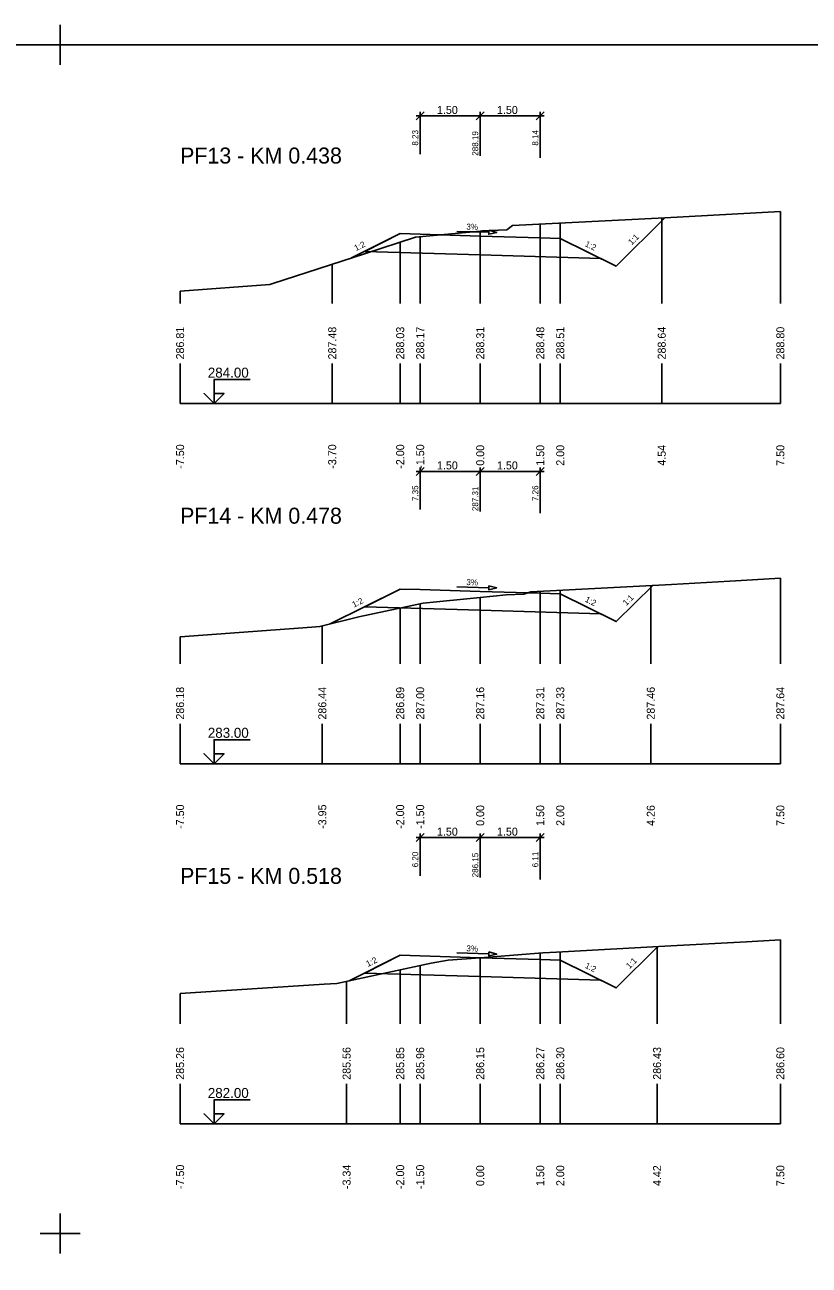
# Model space of a CAD drawing. Extents: x -5 to 1265, y -2 to 602.
# Drawn here: x 831.2 to 1027.2, y 291.7 to 601.7 of the extents above; entities that cross this region are included whole.
import ezdxf

# ---------------------------------------------------------------- set-up
doc = ezdxf.new("R2010")
doc.units = 0
for name, color, linetype in [('KOTA', 7, 'Continuous'), ('KOTA_DELKY', 7, 'Continuous'), ('KOTA_DELKY_CONT', 7, 'Continuous'), ('NS_TELESO_VOZOVKY', 7, 'Continuous'), ('NS_V_PF', 7, 'Continuous'), ('REZY_PF_PUVODNI', 7, 'Continuous'), ('SESTAVY_REZU_PF', 7, 'Continuous'), ('SKLON', 7, 'Continuous'), ('SVK', 7, 'Continuous')]:
    doc.layers.add(name, color=color, linetype=linetype)

msp = doc.modelspace()

# ---------------------------------------------------------------- linework, layer by layer
for p, q in [((840, 601.67), (840, 591.67)), ((840, 601.67), (840, 591.67)), ((840, 601.67), (840, 591.67)), ((840, 601.67), (840, 591.67)), ((840, 601.67), (840, 591.67)), ((840, 601.67), (840, 591.67)), ((840, 601.67), (840, 591.67)), ((840, 601.67), (840, 591.67)), ((840, 601.67), (840, 591.67)), ((840, 601.67), (840, 591.67)), ((840, 601.67), (840, 591.67)), ((840, 601.67), (840, 591.67)), ((840, 601.67), (840, 591.67)), ((840, 601.67), (840, 591.67)), ((840, 601.67), (840, 591.67)), ((840, 601.67), (840, 591.67)), ((840, 601.67), (840, 591.67)), ((840, 601.67), (840, 591.67)), ((840, 601.67), (840, 591.67)), ((840, 601.67), (840, 591.67)), ((840, 601.67), (840, 591.67)), ((840, 601.67), (840, 591.67)), ((840, 601.67), (840, 591.67)), ((840, 601.67), (840, 591.67)), ((840, 601.67), (840, 591.67)), ((840, 601.67), (840, 591.67)), ((840, 601.67), (840, 591.67)), ((840, 601.67), (840, 591.67)), ((840, 601.67), (840, 591.67)), ((840, 601.67), (840, 591.67)), ((840, 601.67), (840, 591.67)), ((840, 601.67), (840, 591.67)), ((840, 601.67), (840, 591.67)), ((840, 601.67), (840, 591.67)), ((840, 601.67), (840, 591.67)), ((840, 601.67), (840, 591.67)), ((840, 601.67), (840, 591.67)), ((840, 601.67), (840, 591.67)), ((840, 601.67), (840, 591.67)), ((840, 601.67), (840, 591.67)), ((840, 601.67), (840, 591.67)), ((840, 601.67), (840, 591.67)), ((840, 601.67), (840, 591.67)), ((840, 601.67), (840, 591.67)), ((840, 601.67), (840, 591.67)), ((840, 601.67), (840, 591.67)), ((840, 601.67), (840, 591.67)), ((840, 601.67), (840, 591.67)), ((840, 601.67), (840, 591.67)), ((840, 601.67), (840, 591.67)), ((840, 601.67), (840, 591.67)), ((840, 601.67), (840, 591.67)), ((840, 601.67), (840, 591.67)), ((840, 601.67), (840, 591.67)), ((845, 596.67), (835, 596.67)), ((845, 596.67), (835, 596.67)), ((845, 596.67), (835, 596.67)), ((845, 596.67), (835, 596.67)), ((845, 596.67), (835, 596.67)), ((845, 596.67), (835, 596.67)), ((845, 596.67), (835, 596.67)), ((845, 596.67), (835, 596.67)), ((845, 596.67), (835, 596.67)), ((845, 596.67), (835, 596.67)), ((845, 596.67), (835, 596.67)), ((845, 596.67), (835, 596.67)), ((845, 596.67), (835, 596.67)), ((845, 596.67), (835, 596.67)), ((845, 596.67), (835, 596.67)), ((845, 596.67), (835, 596.67)), ((845, 596.67), (835, 596.67)), ((845, 596.67), (835, 596.67)), ((845, 596.67), (835, 596.67)), ((845, 596.67), (835, 596.67)), ((845, 596.67), (835, 596.67)), ((845, 596.67), (835, 596.67)), ((845, 596.67), (835, 596.67)), ((845, 596.67), (835, 596.67)), ((845, 596.67), (835, 596.67)), ((845, 596.67), (835, 596.67)), ((845, 596.67), (835, 596.67)), ((845, 596.67), (835, 596.67)), ((845, 596.67), (835, 596.67)), ((845, 596.67), (835, 596.67)), ((845, 596.67), (835, 596.67)), ((845, 596.67), (835, 596.67)), ((845, 596.67), (835, 596.67)), ((845, 596.67), (835, 596.67)), ((845, 596.67), (835, 596.67)), ((845, 596.67), (835, 596.67)), ((845, 596.67), (835, 596.67)), ((845, 596.67), (835, 596.67)), ((845, 596.67), (835, 596.67)), ((845, 596.67), (835, 596.67)), ((845, 596.67), (835, 596.67)), ((845, 596.67), (835, 596.67)), ((845, 596.67), (835, 596.67)), ((845, 596.67), (835, 596.67)), ((845, 596.67), (835, 596.67)), ((845, 596.67), (835, 596.67)), ((845, 596.67), (835, 596.67)), ((845, 596.67), (835, 596.67)), ((845, 596.67), (835, 596.67)), ((845, 596.67), (835, 596.67)), ((845, 596.67), (835, 596.67)), ((845, 596.67), (835, 596.67)), ((845, 596.67), (835, 596.67)), ((845, 596.67), (835, 596.67)), ((840, 304.67), (840, 294.67)), ((840, 304.67), (840, 294.67)), ((840, 304.67), (840, 294.67)), ((840, 304.67), (840, 294.67)), ((840, 304.67), (840, 294.67)), ((840, 304.67), (840, 294.67)), ((840, 304.67), (840, 294.67)), ((840, 304.67), (840, 294.67)), ((840, 304.67), (840, 294.67)), ((840, 304.67), (840, 294.67)), ((840, 304.67), (840, 294.67)), ((840, 304.67), (840, 294.67)), ((840, 304.67), (840, 294.67)), ((840, 304.67), (840, 294.67)), ((840, 304.67), (840, 294.67)), ((840, 304.67), (840, 294.67)), ((840, 304.67), (840, 294.67)), ((840, 304.67), (840, 294.67)), ((840, 304.67), (840, 294.67)), ((840, 304.67), (840, 294.67)), ((840, 304.67), (840, 294.67)), ((840, 304.67), (840, 294.67)), ((840, 304.67), (840, 294.67)), ((840, 304.67), (840, 294.67)), ((840, 304.67), (840, 294.67)), ((840, 304.67), (840, 294.67)), ((840, 304.67), (840, 294.67)), ((840, 304.67), (840, 294.67)), ((840, 304.67), (840, 294.67)), ((840, 304.67), (840, 294.67)), ((840, 304.67), (840, 294.67)), ((840, 304.67), (840, 294.67)), ((840, 304.67), (840, 294.67)), ((840, 304.67), (840, 294.67)), ((840, 304.67), (840, 294.67)), ((840, 304.67), (840, 294.67)), ((840, 304.67), (840, 294.67)), ((840, 304.67), (840, 294.67)), ((840, 304.67), (840, 294.67)), ((840, 304.67), (840, 294.67)), ((840, 304.67), (840, 294.67)), ((840, 304.67), (840, 294.67)), ((840, 304.67), (840, 294.67)), ((840, 304.67), (840, 294.67)), ((840, 304.67), (840, 294.67)), ((840, 304.67), (840, 294.67)), ((840, 304.67), (840, 294.67)), ((840, 304.67), (840, 294.67)), ((840, 304.67), (840, 294.67)), ((840, 304.67), (840, 294.67)), ((840, 304.67), (840, 294.67)), ((840, 304.67), (840, 294.67)), ((840, 304.67), (840, 294.67)), ((840, 304.67), (840, 294.67)), ((840, 304.67), (840, 294.67)), ((840, 304.67), (840, 294.67)), ((840, 304.67), (840, 294.67)), ((840, 304.67), (840, 294.67)), ((840, 304.67), (840, 294.67)), ((840, 304.67), (840, 294.67)), ((840, 304.67), (840, 294.67)), ((840, 304.67), (840, 294.67)), ((840, 304.67), (840, 294.67)), ((840, 304.67), (840, 294.67)), ((840, 304.67), (840, 294.67)), ((840, 304.67), (840, 294.67)), ((845, 299.67), (835, 299.67)), ((845, 299.67), (835, 299.67)), ((845, 299.67), (835, 299.67)), ((845, 299.67), (835, 299.67)), ((845, 299.67), (835, 299.67)), ((845, 299.67), (835, 299.67)), ((845, 299.67), (835, 299.67)), ((845, 299.67), (835, 299.67)), ((845, 299.67), (835, 299.67)), ((845, 299.67), (835, 299.67)), ((845, 299.67), (835, 299.67)), ((845, 299.67), (835, 299.67)), ((845, 299.67), (835, 299.67)), ((845, 299.67), (835, 299.67)), ((845, 299.67), (835, 299.67)), ((845, 299.67), (835, 299.67)), ((845, 299.67), (835, 299.67)), ((845, 299.67), (835, 299.67)), ((845, 299.67), (835, 299.67)), ((845, 299.67), (835, 299.67)), ((845, 299.67), (835, 299.67)), ((845, 299.67), (835, 299.67)), ((845, 299.67), (835, 299.67)), ((845, 299.67), (835, 299.67)), ((845, 299.67), (835, 299.67)), ((845, 299.67), (835, 299.67)), ((845, 299.67), (835, 299.67)), ((845, 299.67), (835, 299.67)), ((845, 299.67), (835, 299.67)), ((845, 299.67), (835, 299.67)), ((845, 299.67), (835, 299.67)), ((845, 299.67), (835, 299.67)), ((845, 299.67), (835, 299.67)), ((845, 299.67), (835, 299.67)), ((845, 299.67), (835, 299.67)), ((845, 299.67), (835, 299.67)), ((845, 299.67), (835, 299.67)), ((845, 299.67), (835, 299.67)), ((845, 299.67), (835, 299.67)), ((845, 299.67), (835, 299.67)), ((845, 299.67), (835, 299.67)), ((845, 299.67), (835, 299.67)), ((845, 299.67), (835, 299.67)), ((845, 299.67), (835, 299.67)), ((845, 299.67), (835, 299.67)), ((845, 299.67), (835, 299.67)), ((845, 299.67), (835, 299.67)), ((845, 299.67), (835, 299.67)), ((845, 299.67), (835, 299.67)), ((845, 299.67), (835, 299.67)), ((845, 299.67), (835, 299.67)), ((845, 299.67), (835, 299.67)), ((845, 299.67), (835, 299.67)), ((845, 299.67), (835, 299.67)), ((845, 299.67), (835, 299.67)), ((845, 299.67), (835, 299.67)), ((845, 299.67), (835, 299.67)), ((845, 299.67), (835, 299.67)), ((845, 299.67), (835, 299.67)), ((845, 299.67), (835, 299.67)), ((845, 299.67), (835, 299.67)), ((845, 299.67), (835, 299.67)), ((845, 299.67), (835, 299.67)), ((845, 299.67), (835, 299.67)), ((845, 299.67), (835, 299.67)), ((845, 299.67), (835, 299.67))]:
    msp.add_line(p, q)
msp.add_lwpolyline([(0, 596.67), (1260, 596.67), (1260, 2.67), (0, 2.67)], close=True)
at = {"layer": 'KOTA'}
for points in [[(878.51, 507), (876.01, 509.5), (878.51, 507), (878.51, 513), (887.51, 513)], [(878.51, 507), (881.01, 509.5), (878.51, 509.5), (878.51, 507)], [(878.51, 507), (881.01, 509.5), (878.51, 509.5)], [(878.51, 417), (876.01, 419.5), (878.51, 417), (878.51, 423), (887.51, 423)], [(878.51, 417), (881.01, 419.5), (878.51, 419.5), (878.51, 417)], [(878.51, 417), (881.01, 419.5), (878.51, 419.5)], [(878.51, 327), (876.01, 329.5), (878.51, 327), (878.51, 333), (887.51, 333)], [(878.51, 327), (881.01, 329.5), (878.51, 329.5), (878.51, 327)], [(878.51, 327), (881.01, 329.5), (878.51, 329.5)]]:
    msp.add_lwpolyline(points, dxfattribs=at)
at = {"layer": 'KOTA_DELKY'}
for points in [[(929, 577.89), (931, 579.89)], [(930, 569.34), (930, 579.89)], [(944, 577.89), (946, 579.89)], [(944, 577.89), (946, 579.89)], [(945, 568.89), (945, 579.89)], [(945, 568.89), (945, 579.89)], [(959, 577.89), (961, 579.89)], [(960, 568.44), (960, 579.89)], [(929, 578.89), (946, 578.89)], [(944, 578.89), (961, 578.89)], [(929, 489.07), (931, 491.07)], [(929, 490.07), (946, 490.07)], [(930, 480.52), (930, 491.07)], [(944, 489.07), (946, 491.07)], [(944, 489.07), (946, 491.07)], [(944, 490.07), (961, 490.07)], [(945, 480.07), (945, 491.07)], [(945, 480.07), (945, 491.07)], [(959, 489.07), (961, 491.07)], [(960, 479.62), (960, 491.07)], [(929, 397.55), (931, 399.55)], [(929, 398.55), (946, 398.55)], [(930, 389), (930, 399.55)], [(944, 397.55), (946, 399.55)], [(944, 397.55), (946, 399.55)], [(944, 398.55), (961, 398.55)], [(945, 388.55), (945, 399.55)], [(945, 388.55), (945, 399.55)], [(959, 397.55), (961, 399.55)], [(960, 388.1), (960, 399.55)]]:
    msp.add_lwpolyline(points, dxfattribs=at)
at = {"layer": 'NS_TELESO_VOZOVKY'}
for points in [[(945, 548.89), (960, 548.44), (965, 548.29), (979.01, 541.36), (975.11, 543.28), (945, 544.19), (916.13, 545.05), (925, 549.49), (930, 549.34), (945, 548.89)], [(945, 460.07), (960, 459.62), (965, 459.47), (979.01, 452.54), (975.11, 454.46), (945, 455.37), (916.13, 456.23), (925, 460.67), (930, 460.52), (945, 460.07)], [(945, 368.55), (960, 368.1), (965, 367.95), (979.01, 361.02), (975.11, 362.95), (945, 363.85), (916.13, 364.72), (925, 369.15), (930, 369), (945, 368.55)]]:
    msp.add_lwpolyline(points, dxfattribs=at)
at = {"layer": 'NS_V_PF'}
for points in [[(912.82, 543.4), (925, 549.49), (930, 549.34), (945, 548.89), (960, 548.44), (965, 548.29), (979.01, 541.36), (991.25, 553.48)], [(907.54, 451.94), (925, 460.67), (930, 460.52), (945, 460.07), (960, 459.62), (965, 459.47), (979.01, 452.54), (988.16, 461.59)], [(912.29, 362.79), (925, 369.15), (930, 369), (945, 368.55), (960, 368.1), (965, 367.95), (979.01, 361.02), (989.41, 371.31)]]:
    msp.add_lwpolyline(points, dxfattribs=at)
at = {"layer": 'REZY_PF_PUVODNI'}
for points in [[(870, 535.09), (892.4, 536.76), (893.21, 537.02), (916.12, 544.47), (928.82, 548.57), (945, 550.14), (945, 550.14), (945.48, 550.19), (951.62, 550.4), (953.05, 551.48), (991.15, 553.47), (1020, 554.98)], [(870, 448.77), (902.92, 451.14), (904.89, 451.28), (914.69, 453.72), (930.75, 457.18), (945, 458.6), (951.52, 459.26), (955.87, 459.42), (957.63, 459.94), (992.77, 461.84), (1007.34, 462.63), (1020, 463.43)], [(870, 359.59), (906.03, 361.92), (909.17, 362.13), (932.77, 367.17), (936.99, 367.9), (945, 368.52), (945, 368.52), (960.63, 369.74), (964.03, 369.94), (992.63, 371.48), (1011.55, 372.51), (1020, 372.98)]]:
    msp.add_lwpolyline(points, dxfattribs=at)
at = {"layer": 'SESTAVY_REZU_PF'}
for points in [[(870, 507), (1020, 507)], [(870, 417), (1020, 417)], [(870, 327), (1020, 327)]]:
    msp.add_lwpolyline(points, dxfattribs=at)
at = {"layer": 'SKLON'}
for points in [[(939.15, 550.06), (947.14, 549.82)], [(947.16, 550.32), (949.14, 549.76), (947.13, 549.32), (947.16, 550.32)], [(939.15, 461.24), (947.14, 461)], [(947.16, 461.5), (949.14, 460.94), (947.13, 460.5), (947.16, 461.5)], [(939.15, 369.73), (947.14, 369.49)], [(947.16, 369.98), (949.14, 369.43), (947.13, 368.99), (947.16, 369.98)]]:
    msp.add_lwpolyline(points, dxfattribs=at)
for points in [[(947.16, 550.32), (949.14, 549.76), (947.13, 549.32)], [(947.16, 461.5), (949.14, 460.94), (947.13, 460.5)], [(947.16, 369.98), (949.14, 369.43), (947.13, 368.99)]]:
    msp.add_lwpolyline(points, close=True, dxfattribs=at)
at = {"layer": 'SVK'}
for points in [[(1020, 532), (1020, 554.98)], [(960, 532), (960, 551.84)], [(965, 532), (965, 552.11)], [(990.36, 532), (990.36, 553.43)], [(930, 532), (930, 548.69)], [(945, 532), (945, 550.14)], [(925, 532), (925, 547.34)], [(908.02, 532), (908.02, 541.84)], [(870, 532), (870, 535.09)], [(870, 507), (870, 517)], [(908.02, 507), (908.02, 517)], [(925, 507), (925, 517)], [(930, 507), (930, 517)], [(945, 507), (945, 517)], [(960, 507), (960, 517)], [(965, 507), (965, 517)], [(990.36, 507), (990.36, 517)], [(1020, 507), (1020, 517)], [(1020, 442), (1020, 463.43)], [(960, 442), (960, 460.06)], [(965, 442), (965, 460.34)], [(987.62, 442), (987.62, 461.56)], [(925, 442), (925, 455.94)], [(930, 442), (930, 457.02)], [(945, 442), (945, 458.6)], [(905.54, 442), (905.54, 451.44)], [(870, 442), (870, 448.77)], [(870, 417), (870, 427)], [(905.54, 417), (905.54, 427)], [(925, 417), (925, 427)], [(930, 417), (930, 427)], [(945, 417), (945, 427)], [(960, 417), (960, 427)], [(965, 417), (965, 427)], [(987.62, 417), (987.62, 427)], [(1020, 417), (1020, 427)], [(1020, 352), (1020, 372.98)], [(960, 352), (960, 369.69)], [(965, 352), (965, 369.99)], [(989.2, 352), (989.2, 371.3)], [(930, 352), (930, 366.58)], [(945, 352), (945, 368.52)], [(925, 352), (925, 365.51)], [(870, 352), (870, 359.59)], [(911.61, 352), (911.61, 362.65)], [(870, 327), (870, 337)], [(911.61, 327), (911.61, 337)], [(925, 327), (925, 337)], [(930, 327), (930, 337)], [(945, 327), (945, 337)], [(960, 327), (960, 337)], [(965, 327), (965, 337)], [(989.2, 327), (989.2, 337)], [(1020, 327), (1020, 337)]]:
    msp.add_lwpolyline(points, dxfattribs=at)

# ---------------------------------------------------------------- texts
at = {"layer": 'KOTA'}
for s, p in [('284.00', (876.93, 513.5)), ('283.00', (876.93, 423.5)), ('282.00', (876.93, 333.5))]:
    msp.add_text(s, height=2.5, dxfattribs=at).set_placement(p)
at = {"layer": 'KOTA_DELKY'}
for p in [(934.19, 579.39), (949.19, 579.39), (934.19, 490.57), (949.19, 490.57), (934.19, 399.05), (949.19, 399.05)]:
    msp.add_text('1.50', height=2, dxfattribs=at).set_placement(p)
at = {"layer": 'KOTA_DELKY_CONT'}
for s, p in [('8.23', (929.5, 571.48)), ('288.19', (944.5, 568.96)), ('8.14', (959.5, 571.48)), ('7.35', (929.5, 482.66)), ('287.31', (944.5, 480.14)), ('7.26', (959.5, 482.66)), ('6.20', (929.5, 391.14)), ('286.15', (944.5, 388.63)), ('6.11', (959.5, 391.14))]:
    msp.add_text(s, height=1.5, rotation=90, dxfattribs=at).set_placement(p)
at = {"layer": 'SESTAVY_REZU_PF'}
for s, p in [('PF13 - KM 0.438', (870, 567)), ('PF14 - KM 0.478', (870, 477)), ('PF15 - KM 0.518', (870, 387))]:
    msp.add_text(s, height=4, dxfattribs=at).set_placement(p)
at = {"layer": 'SKLON'}
for s, rotation, p in [('3%', 358.2816, (941.52, 550.49)), ('1:1', 44.7149, (982.84, 546.55)), ('1:2', 26.5651, (913.97, 545.09)), ('1:2', 333.679, (971.04, 546.42)), ('3%', 358.2816, (941.52, 461.67)), ('1:1', 44.7149, (981.5, 456.4)), ('1:2', 26.5651, (913.44, 456.01)), ('1:2', 333.679, (971.04, 457.6)), ('3%', 358.2816, (941.52, 370.15)), ('1:2', 26.5651, (916.93, 366.23)), ('1:2', 333.679, (971.04, 366.08)), ('1:1', 44.7149, (982.31, 365.69))]:
    msp.add_text(s, height=1.5, rotation=rotation, dxfattribs=at).set_placement(p)
at = {"layer": 'SVK'}
for s, p in [(' 286.81', (871, 517.3)), (' 287.48', (909.02, 517.3)), (' 288.03', (926, 517.3)), (' 288.17', (931, 517.3)), (' 288.31', (946, 517.3)), (' 288.48', (961, 517.3)), (' 288.51', (966, 517.3)), (' 288.64', (991.36, 517.3)), (' 288.80', (1021, 517.3)), (' -7.50', (871, 490)), (' -3.70', (909.02, 490)), (' -2.00', (926, 490)), (' -1.50', (931, 490)), ('  0.00', (946, 490)), ('  1.50', (961, 490)), ('  2.00', (966, 490)), ('  4.54', (991.36, 490)), ('  7.50', (1021, 490)), (' 286.18', (871, 427.3)), (' 286.44', (906.54, 427.3)), (' 286.89', (926, 427.3)), (' 287.00', (931, 427.3)), (' 287.16', (946, 427.3)), (' 287.31', (961, 427.3)), (' 287.33', (966, 427.3)), (' 287.46', (988.62, 427.3)), (' 287.64', (1021, 427.3)), (' -7.50', (871, 400)), (' -3.95', (906.54, 400)), (' -2.00', (926, 400)), (' -1.50', (931, 400)), ('  0.00', (946, 400)), ('  1.50', (961, 400)), ('  2.00', (966, 400)), ('  4.26', (988.62, 400)), ('  7.50', (1021, 400)), (' 285.26', (871, 337.3)), (' 285.56', (912.61, 337.3)), (' 285.85', (926, 337.3)), (' 285.96', (931, 337.3)), (' 286.15', (946, 337.3)), (' 286.27', (961, 337.3)), (' 286.30', (966, 337.3)), (' 286.43', (990.2, 337.3)), (' 286.60', (1021, 337.3)), (' -7.50', (871, 310)), (' -3.34', (912.61, 310)), (' -2.00', (926, 310)), (' -1.50', (931, 310)), ('  0.00', (946, 310)), ('  1.50', (961, 310)), ('  2.00', (966, 310)), ('  4.42', (990.2, 310)), ('  7.50', (1021, 310))]:
    msp.add_text(s, height=2, rotation=90, dxfattribs=at).set_placement(p)

doc.saveas('drawing.dxf')
